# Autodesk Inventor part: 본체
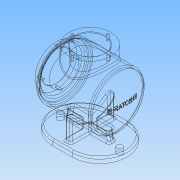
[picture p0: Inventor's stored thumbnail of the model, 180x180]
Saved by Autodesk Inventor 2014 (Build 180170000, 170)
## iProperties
Created: 2016-04
Part Number: 본체
Material: 알루미늄 6061
Document SubType Name: Modeling
Designer: 601-
Density: 2.71 g/cm^3
Appearance: 알루미늄 - 평지
Mass: 948.525 g
Surface Area: 1271.5 cm^2
Volume: 350.009 cm^3
Author: 601-
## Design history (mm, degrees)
sketch "스케치1"
  geometry: L1 (67.5, -50)-(-67.5, -50); L2 (-67.5, -50)-(-67.5, 50); L3 (-67.5, 50)-(67.5, 50); L4 (67.5, 50)-(67.5, -50); L5 (67.5, -50)-(-67.5, 50); L6 (-67.5, -50)-(67.5, 50); L7 (-17.5, 50)-(-17.5, -50); L8 (17.5, 50)-(17.5, -50); L9 (-17.5, 50)-(17.5, 50); L10 (-17.5, -50)-(17.5, -50); 5 further points; 2 other entities
  constraints: 20 end point, 7 horizontal, 5 midpoint, 4 point on line, 3 perpendicular, 2 parallel, 1 coincident, 1 vertical, 8 other
  dimensions: "d0" = 135 distance of L2.end L3.end; "d1" = 100 distance of L3.end L1.start; "d2" = 50 distance between parallel lines of L2 L7; "d3" = 50 distance between parallel lines of L4 L8
extrude "돌출1" new body sketch "스케치1" distance "d4" = 10; taper "d5" = 0 deg
sketch "스케치6"
  geometry: L1 (-17.5, 10)-(-67.5, 10) reference; L2 (67.5, 10)-(17.5, 10) reference; L3 (-17.5, 10)-(17.5, 10) reference; L4 (-40, 10)-(-26.07, 89); L5 (-26.07, 89)-(26.07, 89); L6 (26.07, 89)-(40, 10); L7 (0, 0)-(0, 30.754)
  constraints: 8 end point, 2 point on line, 1 parallel, 1 perpendicular
  dimensions: "d15" = 40 distance from line of L4.start L7; "d16" = 40 distance from line of L6.end L7; "d17" = 100 deg angle of L2 L6; "d18" = 100 deg angle of L1 L4; "d19" = 79 distance between parallel lines of L2 L5
extrude "돌출2" join sketch "스케치6" stored distance "d20" = 10; taper "d21" = 0 deg
sketch "스케치7"
  geometry: L1 (-40, 10)-(-40, 89); L2 (-40, 89)-(40, 89); L3 (40, 89)-(40, 10); L4 (50, 0)-(-50, 0) reference; L5 (-40, 10)-(40, 10); 2 further points
  constraints: 8 end point, 1 coincident, 1 parallel, 1 perpendicular
  dimensions: "d22" = 40 distance from line of point (0, 0) L1; "d23" = 40 distance from line of point (0, 0) L3; "d24" = 89 distance between parallel lines of L4 L2
extrude "돌출3" join sketch "스케치7" stored distance "d25" = 10; taper "d26" = 0 deg
sketch "스케치8"
  geometry: L1 (50, 79)-(-50, 79); L2 (-50, 79)-(-50, 129); L3 (-50, 129)-(50, 129); L4 (50, 129)-(50, 79); L5 (50, 79)-(-50, 129); L6 (-50, 79)-(50, 129); L7 (-17.5, 0)-(-67.5, 0) reference; L8 (-17.5, 0)-(17.5, 0) reference; 4 further points
  constraints: 12 end point, 4 midpoint, 2 parallel, 1 horizontal, 1 perpendicular, 1 vertical alignment
  dimensions: "d27" = 79 distance between parallel lines of L7 L1; "d29" = 100 diameter of L3 L1; "d30" = 100 distance of L2.end L3.end
revolve "회전1" sketch "스케치8" stored, may be unused: angle "d31" = 90 deg
sketch "스케치9"
  geometry: C1 r 50 at (0, 0) reference; C2 r 38 at (0, 0); 1 further point
  constraints: 1 centre point, 1 coincident
  dimensions: "d32" = 76 diameter of C2
extrude "돌출4" join sketch "스케치9" distance "d33" = 12; taper "d34" = 0 deg
sketch "스케치10"
  geometry: L1 (17.5, 0)-(-17.5, 0) reference; L2 (-38, 129)-(-38, 144); L3 (-38, 144)-(0, 144); L4 (0, 144)-(0, 129); L5 (-17.5, 0)-(-67.5, 0) reference; L6 (-38, 129)-(-38, 98.072); L7 (-50, 129)-(50, 129) reference; L8 (-38, 98.072)-(0, 98.072); L9 (0, 98.072)-(0, 129); 2 further points
  constraints: 12 end point, 2 parallel, 2 perpendicular, 1 midpoint
  dimensions: "d37" = 76 diameter of L2 L4; "d38" = 144 distance between parallel lines of L5 L3
revolve "회전2" sketch "스케치10" stored, may be unused: angle "d39" = 90 deg
sketch "스케치11"
  geometry: 3 further points
  dimensions: "d40" = 54 distance of point (0, 0) point (-54, 0); "d41" = 54 distance of point (0, 0) point (54, 0)
hole "구멍1" sketch "스케치11" at (-54, 0), (54, 0) diameter "d42" = 10; stored, may be unused: countersink angle "d46" = 90 deg, drill point angle "d48" = 118 deg; dims "d43" = 6, "d44" = 4, "d45" = 2, "d47" = 8
sketch "스케치12" dims "d49" = 65
  geometry: C1 r 38 at (0, 0) reference; 3 further points
  constraints: 1 coincident, 1 vertical alignment, 2 other
hole "구멍2" sketch "스케치12" at (0, 32.5) diameter "d50" = 3.242; stored, may be unused: countersink angle "d54" = 90 deg, drill point angle "d56" = 118 deg; dims "d51" = 8, "d52" = 4, "d53" = 2, "d55" = 10
chamfer "모따기1" distance "d60" = 3; stored, may be unused: second distance "d61" = 2, angle "d62" = 45 deg
fillet "모깎기1" dims "d63" = 3
fillet "모깎기2" dims "d64" = 3, "d92" = 5
sketch "스케치13"
  geometry: L1 (-60.913, 79)-(59.087, 79); L2 (67.5, 0)-(17.5, 0) reference; L3 (-50, 129)-(-50, 29); L4 (-60.913, 79)-(-50, 79); L5 (-50, 29)-(-50, 129) reference; L6 (-50, 129)-(-50, 79); A1 r 120 centre (59.087, 79) between (-50, 129) and (-50, 29); 1 further point
  constraints: 8 end point, 3 point on circle, 1 centre point, 1 collinear, 1 midpoint
  dimensions: "d70" = 120 distance of L1.start L1.end; "d72" = 79 distance between parallel lines of L2 L1; "d112" = 120 radius of A1
revolve "회전3" sketch "스케치13" stored, may be unused: angle "d69" = 90 deg
sketch "스케치15"
  geometry: L1 (-50, 129)-(45, 129) reference; L2 (-48.058, 126)-(47, 126); L3 (-57.913, 79)-(44.087, 79); L4 (47, 126)-(47, 79); L5 (47, 79)-(44.087, 79); L6 (50, 38)-(50, 120) reference; A1 r 120 centre (59.087, 79) between (-50, 129) and (-50, 29) reference; A2 r 117 centre (59.087, 79) between (-48.058, 126) and (-57.913, 79); 1 further point
  constraints: 8 end point, 2 parallel, 2 perpendicular, 2 point on circle, 1 centre point
  dimensions: "d73" = 3 radial gap between concentric circles of A1 A2; "d74" = 3 distance between parallel lines of L1 L2; "d111" = 3 distance from line of L6 L4.end
revolve "회전4" sketch "스케치15" stored, may be unused: angle "d75" = 90 deg
sketch "스케치16"
  geometry: C1 r 38 at (0, 0) reference; 1 further point
hole "구멍3" sketch "스케치16" at (0, 0) diameter "d76" = 54; stored, may be unused: countersink angle "d80" = 90 deg, drill point angle "d82" = 0 deg; dims "d77" = 8, "d78" = 4, "d79" = 2, "d81" = 30
sketch "스케치17"
  geometry: C1 r 38 at (0, 0) reference
hole "구멍4" sketch "스케치17" at (0, 0) diameter "d83" = 54; stored, may be unused: countersink angle "d87" = 90 deg, drill point angle "d89" = 0 deg; dims "d84" = 8, "d85" = 4, "d86" = 2, "d88" = 50
fillet "모깎기3" dims "d90" = 5, "d91" = 2
chamfer "모따기2" distance "d93" = 1; stored, may be unused: second distance "d94" = 2, angle "d95" = 45 deg
sketch "스케치18"
  geometry: C1 r 38 at (0, 0) reference; 1 further point
  dimensions: "d96" = 32.5 distance of C1.centre point (0, 32.5)
hole "구멍5" sketch "스케치18" at (0, 32.5) diameter "d97" = 3.242; stored, may be unused: countersink angle "d101" = 90 deg, drill point angle "d103" = 118 deg; dims "d98" = 8, "d99" = 4, "d100" = 2, "d102" = 10
node "작업 평면1"
sketch "스케치20"
  geometry: 2 further points
  constraints: 1 vertical alignment, 1 other
  dimensions: "d108" = 79 distance of point (0, 0) point (0, 79)
feature "엠보싱1" sketch "스케치20" dims "d0" = 135, "d1" = 100, "d2" = 50, "d3" = 50, "d109" = 0.5, "d110" = 0
node "솔리드1"
pattern_circular "원형 패턴1" dims angle "d58" = 360 deg
pattern_circular "원형 패턴2" dims angle "d105" = 360 deg
